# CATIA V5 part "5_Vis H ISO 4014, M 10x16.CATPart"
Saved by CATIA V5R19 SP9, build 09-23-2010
Part number: 5_Vis H ISO 4014, M 10x16
Revision: ANY
Definition: UNKNOWN
Nomenclature: 5_Vis H ISO 4014, M 10x16
Source: Unknown
Bounding box of the stored display mesh (mm): x -9.238 to 9.238, y -16 to 6.4, z -8 to 8
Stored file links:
  Y:\fin de projet cabestan poupee\5_Vis H ISO 4014, M 10x16.CATPart
  Ass_arbre poupee_1.CATProduct
  Y:\bricolage cabestan\6_axe.CATPart
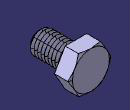
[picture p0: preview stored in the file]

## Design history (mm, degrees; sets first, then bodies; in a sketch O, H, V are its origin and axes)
Body1 "NONE" (main body)
  Solid1: solid without history
Body2
  Solid2 "NONE": solid without history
